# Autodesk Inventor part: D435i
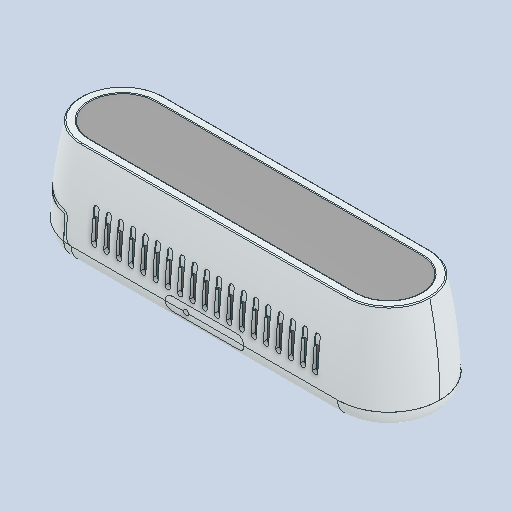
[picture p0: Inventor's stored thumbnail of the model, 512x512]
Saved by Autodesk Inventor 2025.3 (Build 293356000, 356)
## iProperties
Created: 2018-08
Part Number: D435i
Material: Genérico
Document SubType Name: Modeling
Designer: Luis MuÃ±oz
Density: 1 g/cm^3
Appearance: Valor por defecto
Project: TESIS 2 - Plataforma mecatrÃ³nica preventiva desacoplada
Description: Cámara de profundidad Intel RealSense D435i
Vendor: Intel RealSense
Sending System: SolidWorks 2016
Last Author: Ancel
Last Saved: 2018-09-21
Author: Luis M
Title: CÃ¡mara de profundidad Intel RealSense D435i
Revision Number: 00
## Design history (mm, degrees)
thread "Split2[2]"
thread "Thread1"
thread "Cut-Extrude10[1]"
thread "Cut-Extrude10[2]"
thread "Cut-Extrude12"
node "Plane1"
node "Plane2"
node "Plane3"
node "Plane4"
node "Plane5"
node "Plane6"
node "Plane7"
node "Plane8"
node "Sólido1"
node "Sólido2"
node "Sólido3"
node "Sólido4"
node "Sólido5"
